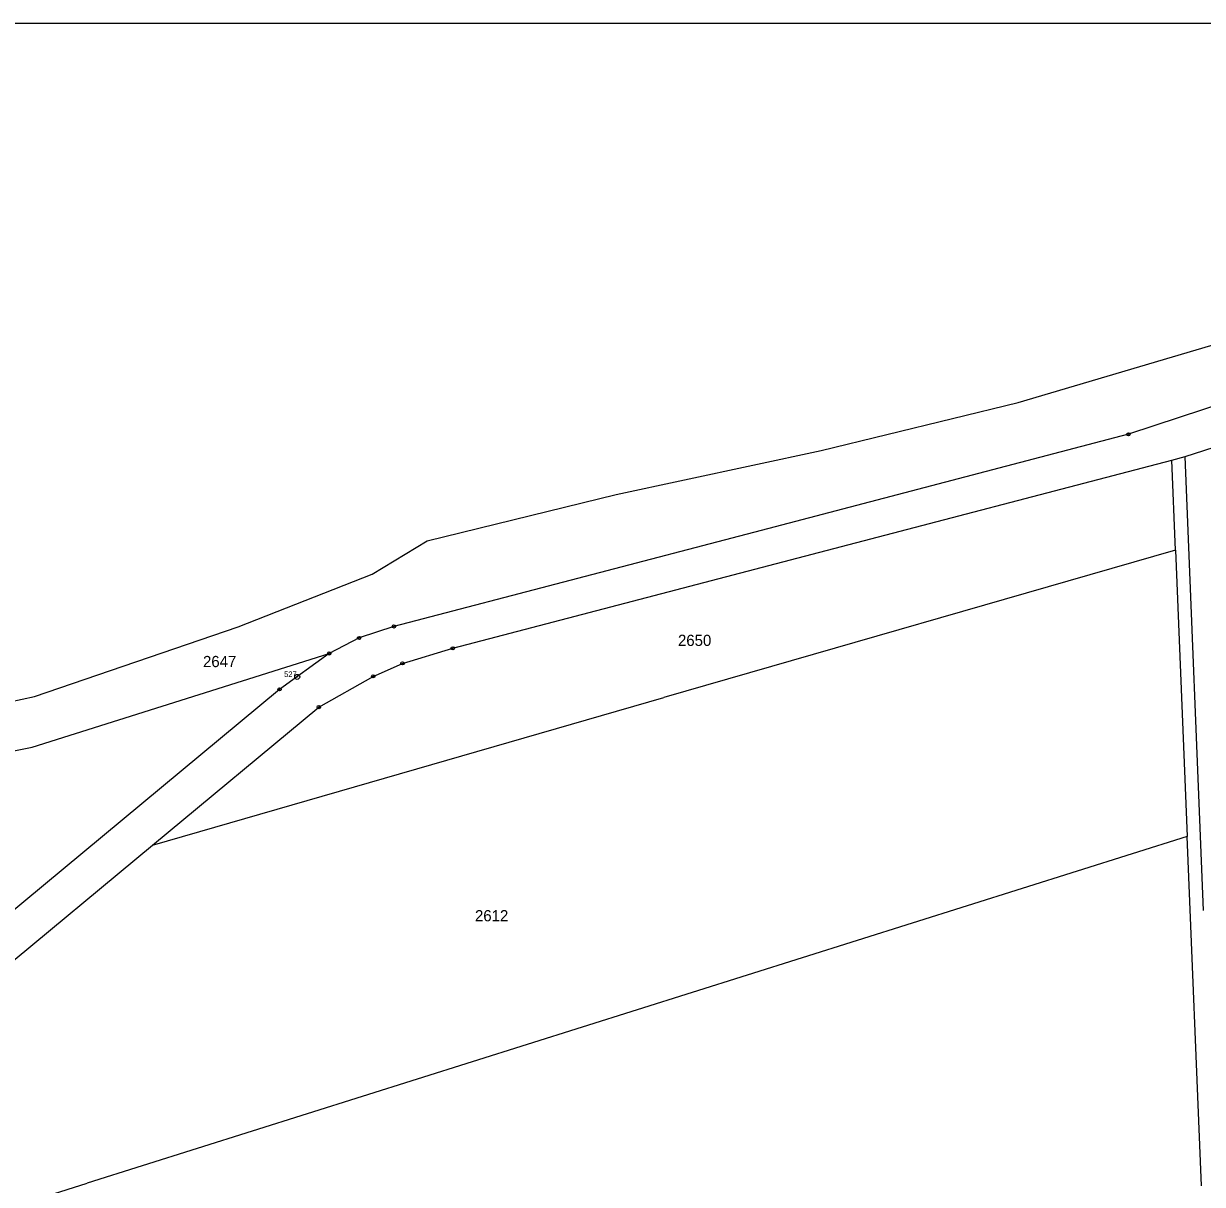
# Model space of a CAD drawing. Extents: x -565355 to -564154, y -1097649 to -1095548.
# Drawn here: x -564696.7 to -564338.5, y -1095900.6 to -1095547.8 of the extents above; entities that cross this region are included whole.
import ezdxf

# ---------------------------------------------------------------- set-up
doc = ezdxf.new("R2010")
doc.units = 0
for name, color, linetype in [('Vrstva 1', 7, 'Continuous'), ('Vrstva 13', 7, 'Continuous'), ('Vrstva 17', 7, 'Continuous'), ('Vrstva 18', 7, 'Continuous'), ('Vrstva 24', 7, 'Continuous'), ('Vrstva 63', 7, 'Continuous')]:
    doc.layers.add(name, color=color, linetype=linetype)

msp = doc.modelspace()

# ---------------------------------------------------------------- linework, layer by layer
at = {"layer": 'Vrstva 1'}
for p, q in [((-564329.81, -1095662.26), (-564361.01, -1095672.63)), ((-564361.01, -1095672.63), (-564472.59, -1095701.81)), ((-564343.82, -1095679.33), (-564332.14, -1095675.66)), ((-564457.04, -1095709.06), (-564347.78, -1095680.45)), ((-564347.78, -1095680.45), (-564343.82, -1095679.33)), ((-564346.67, -1095707.8), (-564347.78, -1095680.45)), ((-564338.22, -1095817.34), (-564343.82, -1095679.33)), ((-564472.59, -1095701.81), (-564584.17, -1095730.99)), ((-564566.29, -1095737.66), (-564457.04, -1095709.06)), ((-564346.67, -1095707.8), (-564502.1, -1095752.64)), ((-564346.67, -1095707.8), (-564343.14, -1095794.87)), ((-564584.17, -1095730.99), (-564594.74, -1095734.52)), ((-564594.74, -1095734.52), (-564603.8, -1095739.23)), ((-564694, -1095767.75), (-564603.8, -1095739.23)), ((-564603.8, -1095739.23), (-564618.9, -1095750.13)), ((-564581.56, -1095742.23), (-564566.29, -1095737.66)), ((-564590.41, -1095746.18), (-564581.56, -1095742.23)), ((-564606.99, -1095755.53), (-564590.41, -1095746.18)), ((-564618.9, -1095750.13), (-564702.52, -1095819.63)), ((-564657.54, -1095797.49), (-564502.1, -1095752.64)), ((-564657.54, -1095797.49), (-564606.99, -1095755.53)), ((-564877.52, -1095802.97), (-564694, -1095767.75)), ((-564343.14, -1095794.87), (-564510.24, -1095847.52)), ((-564338.84, -1095900.99), (-564343.14, -1095794.87)), ((-564732.82, -1095859.97), (-564657.54, -1095797.49)), ((-564510.24, -1095847.52), (-564677.35, -1095900.18)), ((-564844.45, -1095952.83), (-564677.35, -1095900.18))]:
    msp.add_line(p, q, dxfattribs=at)
at = {"layer": 'Vrstva 13'}
for p, q in [((-564394.52, -1095662.95), (-564326.21, -1095642.73)), ((-564454.33, -1095677.56), (-564394.52, -1095662.95)), ((-564516.6, -1095690.89), (-564454.33, -1095677.56)), ((-564574.04, -1095705.03), (-564516.6, -1095690.89)), ((-564590.74, -1095715.12), (-564574.04, -1095705.03)), ((-564631.48, -1095731.18), (-564590.74, -1095715.12)), ((-564693.31, -1095752.31), (-564631.48, -1095731.18)), ((-564772.2, -1095768.91), (-564693.31, -1095752.31))]:
    msp.add_line(p, q, dxfattribs=at)
at = {"layer": 'Vrstva 24'}
for centre, radius in [((-564361.01, -1095672.63), 0.5), ((-564361.01, -1095672.63), 0.0327), ((-564584.17, -1095730.99), 0.5), ((-564584.17, -1095730.99), 0.0327), ((-564594.74, -1095734.52), 0.5), ((-564594.74, -1095734.52), 0.0327), ((-564603.8, -1095739.23), 0.5), ((-564603.8, -1095739.23), 0.0327), ((-564566.29, -1095737.66), 0.5), ((-564566.29, -1095737.66), 0.0327), ((-564581.56, -1095742.23), 0.5), ((-564581.56, -1095742.23), 0.0327), ((-564613.52, -1095746.34), 0.75), ((-564613.52, -1095746.34), 0.0327), ((-564590.41, -1095746.18), 0.5), ((-564590.41, -1095746.18), 0.0327), ((-564618.9, -1095750.13), 0.5), ((-564618.9, -1095750.13), 0.0327), ((-564606.99, -1095755.53), 0.5), ((-564606.99, -1095755.53), 0.0327)]:
    msp.add_circle(centre, radius, dxfattribs=at)
at = {"layer": 'Vrstva 63'}
msp.add_line((-564154.77, -1095547.8), (-565342.77, -1095547.8), dxfattribs=at)

# ---------------------------------------------------------------- texts
at = {"layer": 'Vrstva 17'}
msp.add_text('527', height=1.7, dxfattribs=at).set_placement((-564617.49, -1095746.39))
at = {"layer": 'Vrstva 18'}
for s, p in [('2650', (-564497.85, -1095736.94)), ('2647', (-564642.15, -1095743.37)), ('2612', (-564559.52, -1095820.62))]:
    msp.add_text(s, height=3.4, dxfattribs=at).set_placement(p)

doc.saveas('drawing.dxf')
